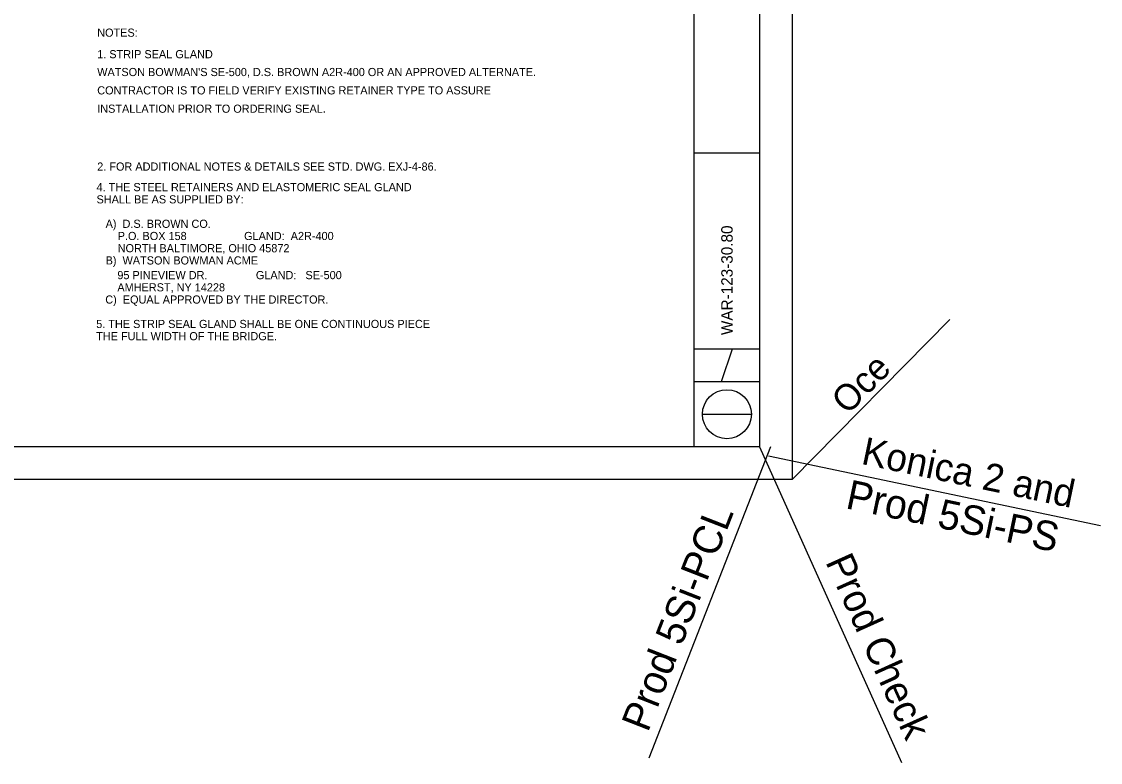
# Model space of a CAD drawing. Extents: x -706 to 14950, y -1867 to 6417.
# Drawn here: x 454 to 949.8, y -1866.6 to -1526.3 of the extents above; entities that cross this region are included whole.
import ezdxf

# ---------------------------------------------------------------- set-up
doc = ezdxf.new("R2010")
doc.units = 0
for name, color, linetype in [('Level 1', 7, 'Continuous'), ('Level 42', 7, 'Continuous'), ('Level 43', 7, 'Continuous'), ('Level 44', 7, 'Continuous')]:
    doc.layers.add(name, color=color, linetype=linetype)

msp = doc.modelspace()

# ---------------------------------------------------------------- linework, layer by layer
at = {"layer": 'Level 1'}
for p, q in [((763.17, -1721.66), (763.17, -1091.66)), ((763.17, -1586.66), (793.17, -1586.66)), ((763.17, -1676.66), (793.17, -1676.66)), ((775.67, -1691.66), (780.67, -1676.66)), ((763.17, -1691.66), (793.17, -1691.66)), ((766.92, -1706.66), (789.42, -1706.66))]:
    msp.add_line(p, q, dxfattribs=at)
for points in [[(-211.83, -1076.66), (808.17, -1076.66), (808.17, -1736.66), (-211.83, -1736.66)], [(-151.83, -1091.66), (793.17, -1091.66), (793.17, -1721.66), (-151.83, -1721.66)]]:
    msp.add_lwpolyline(points, close=True, dxfattribs=at)
msp.add_circle((778.17, -1706.66), 11.25, dxfattribs=at)
at = {"layer": 'Level 43'}
for p, q in [((808.17, -1736.66), (880.62, -1663.14)), ((798.17, -1721.66), (742.31, -1864.63)), ((793.17, -1721.66), (858.44, -1866.58)), ((797.32, -1725.81), (949.78, -1757.7))]:
    msp.add_line(p, q, dxfattribs=at)

# ---------------------------------------------------------------- texts
at = {"layer": 'Level 1'}
msp.add_text('  WAR-123-30.80 ', height=5.25, rotation=90, dxfattribs=at).set_placement((780.8, -1674.2))
at = {"layer": 'Level 42'}
for s, p in [('4. THE STEEL RETAINERS AND ELASTOMERIC SEAL GLAND', (488.49, -1604.22)), ('SHALL BE AS SUPPLIED BY:', (488.49, -1609.83)), ('   A)  D.S. BROWN CO.                 ', (488.49, -1621.05)), ('       P.O. BOX 158                   GLAND:  A2R-400', (488.49, -1626.66)), ('       NORTH BALTIMORE, OHIO 45872', (488.49, -1632.27)), ('   B)  WATSON BOWMAN ACME             ', (488.49, -1637.88)), ('       95 PINEVIEW DR.                GLAND:   SE-500', (488.33, -1644.63)), ('       AMHERST, NY 14228', (488.33, -1650.24)), ('   C)  EQUAL APPROVED BY THE DIRECTOR.', (488.33, -1655.85)), ('5. THE STRIP SEAL GLAND SHALL BE ONE CONTINUOUS PIECE', (488.33, -1667.07)), ('THE FULL WIDTH OF THE BRIDGE.', (488.33, -1672.68))]:
    msp.add_text(s, height=3.74, dxfattribs=at).set_placement(p)
at = {"layer": 'Level 43'}
for s, height, rotation, p in [('Oce', 12, 45.4212, (833.62, -1707.27)), ('Konica 2 and', 12.696, 348.1867, (839.42, -1729.43)), ('Prod 5Si-PS', 13.4513, 348.1871, (832.22, -1749.79)), ('Prod 5Si-PCL', 13.3255, 68.6595, (741.81, -1853.15)), ('Prod Check', 12.987, 294.245, (823.26, -1774.41))]:
    msp.add_text(s, height=height, rotation=rotation, dxfattribs=at).set_placement(p)
at = {"layer": 'Level 44'}
for s, height, p in [('NOTES:', 3.742, (488.8, -1533.27)), ('1. STRIP SEAL GLAND', 3.7418, (488.8, -1543.16)), ("WATSON BOWMAN'S SE-500, D.S. BROWN A2R-400 OR AN APPROVED ALTERNATE.", 3.7406, (488.8, -1551.35)), ('CONTRACTOR IS TO FIELD VERIFY EXISTING RETAINER TYPE TO ASSURE ', 3.7406, (488.8, -1559.77)), ('INSTALLATION PRIOR TO ORDERING SEAL.', 3.7406, (488.8, -1568.19)), ('2. FOR ADDITIONAL NOTES & DETAILS SEE STD. DWG. EXJ-4-86.', 3.7418, (488.8, -1594.77))]:
    msp.add_text(s, height=height, dxfattribs=at).set_placement(p)

doc.saveas('drawing.dxf')
